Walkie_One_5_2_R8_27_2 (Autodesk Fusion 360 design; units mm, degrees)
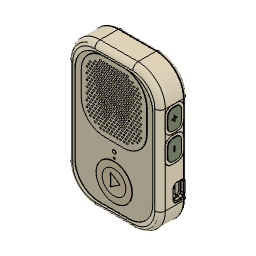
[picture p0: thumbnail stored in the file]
description: Part Number
part number: 2026-09-09-11-52-02-632
part number: 2026-09-09-11-52-02-876
part number: 2026-09-09-11-52-02-878
part number: Open CASCADE STEP translator 7.7 1
part number: 2026-09-09-11-52-03-255
part number: Open CASCADE STEP translator 7.7 2
part number: 2026-09-09-11-52-03-357
part number: Open CASCADE STEP translator 7.7 3
part number: 2026-09-09-11-52-03-466
part number: Open CASCADE STEP translator 7.7 4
